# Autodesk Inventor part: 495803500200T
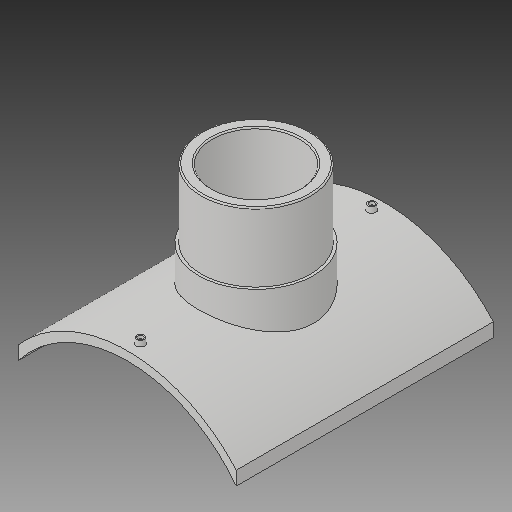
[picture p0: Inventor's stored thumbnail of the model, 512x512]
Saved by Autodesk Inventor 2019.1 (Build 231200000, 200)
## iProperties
Created: 2017-10
Part Number: 495803500200T
Material: Generic
Description: PLASSON BRANCH SADDLE  500x200
Document SubType Name: Modeling
Designer: KIM
Mass: 2754.05 g
Surface Area: 3037.44 cm^2
Volume: 2754.05 cm^3
Density: 1 g/cm^3
Appearance: Default
Author: KIM
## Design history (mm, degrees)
derived "495803.ipt"
feature "Solid1::495803.ipt"
tag "TaggingFeature1"
body "Solid1"
other parameters: "d1" = 16, "d2" = 398, "d4" = 0, "d12" = 275.6, "d13" = 14, "d14" = 211.5, "d16" = 5 deg, "d18" = 4, "d19" = 14, "d20" = 0, "d21" = 3, "d22" = 0, "d23" = 446, "d25" = 16, "d28" = 0, "d29" = 9.6, "d31" = 0, "d33" = 0, "d34" = 5, "d37" = 126, "d38" = 0, "d39" = 2.5, "B_" = 398, "x_" = 16, "D_" = 16
